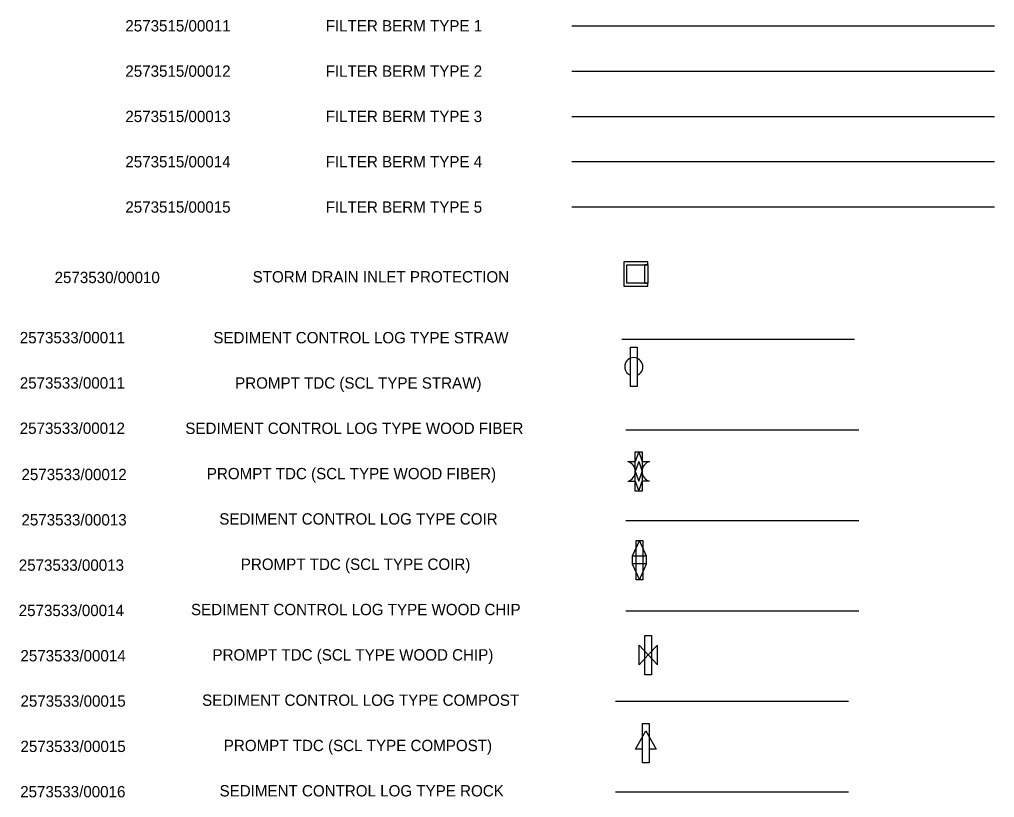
# Model space of a CAD drawing. Extents: x 2147712 to 2176316, y 2125036 to 2131746.
# Drawn here: x 2155076 to 2155722, y 2127332 to 2127847 of the extents above; entities that cross this region are included whole.
import ezdxf

# ---------------------------------------------------------------- set-up
doc = ezdxf.new("R2010")
doc.units = 0
doc.layers.add('DETAIL TXT', color=7, linetype='Continuous')
doc.layers.add('ERSN CTRL', color=7, linetype='Continuous')

msp = doc.modelspace()

# ---------------------------------------------------------------- linework, layer by layer
at = {"layer": 'ERSN CTRL'}
for p, q in [((2155442.09, 2127842.98), (2155722.13, 2127842.98)), ((2155442.09, 2127812.98), (2155722.13, 2127812.98)), ((2155442.09, 2127782.98), (2155722.13, 2127782.98)), ((2155442.09, 2127752.98), (2155722.13, 2127752.98)), ((2155442.09, 2127722.98), (2155722.13, 2127722.98)), ((2155484.13, 2127534.88), (2155484.13, 2127560.88)), ((2155484.13, 2127560.88), (2155488.58, 2127560.88)), ((2155486.36, 2127560.88), (2155484.13, 2127554.38)), ((2155486.36, 2127560.88), (2155488.58, 2127554.38)), ((2155488.58, 2127560.88), (2155488.58, 2127534.88)), ((2155479.13, 2127554.38), (2155484.13, 2127554.38)), ((2155486.36, 2127554.38), (2155484.13, 2127547.88)), ((2155486.36, 2127554.38), (2155488.58, 2127547.88)), ((2155488.58, 2127554.38), (2155493.58, 2127554.38)), ((2155484.13, 2127547.88), (2155486.36, 2127541.38)), ((2155486.36, 2127541.38), (2155488.58, 2127547.88)), ((2155479.13, 2127541.38), (2155484.13, 2127541.38)), ((2155484.13, 2127541.38), (2155486.36, 2127534.88)), ((2155486.36, 2127534.88), (2155488.58, 2127541.38)), ((2155493.58, 2127541.38), (2155488.58, 2127541.38)), ((2155488.58, 2127534.88), (2155484.13, 2127534.88)), ((2155484.59, 2127476.21), (2155484.59, 2127502.21)), ((2155484.59, 2127502.21), (2155489.04, 2127502.21)), ((2155489.04, 2127502.21), (2155489.04, 2127476.21)), ((2155491.54, 2127491.71), (2155482.09, 2127491.71)), ((2155491.54, 2127486.71), (2155482.09, 2127486.71)), ((2155489.04, 2127476.21), (2155484.59, 2127476.21))]:
    msp.add_line(p, q, dxfattribs=at)
for points in [[(2155492.53, 2127686.62), (2155476.53, 2127686.62), (2155476.53, 2127670.62), (2155492.53, 2127670.62), (2155492.53, 2127672.62), (2155478.53, 2127672.62), (2155478.53, 2127684.62), (2155492.53, 2127684.62)], [(2155490.53, 2127684.62), (2155492.53, 2127684.62), (2155492.53, 2127684.62), (2155490.53, 2127684.62)], [(2155490.53, 2127684.62), (2155492.53, 2127684.62), (2155492.53, 2127672.62), (2155490.53, 2127672.62)], [(2155492.53, 2127672.62), (2155490.53, 2127672.62), (2155490.53, 2127672.62), (2155492.53, 2127672.62)], [(2155486.82, 2127476.21), (2155491.54, 2127486.71), (2155491.54, 2127491.71), (2155486.82, 2127502.21), (2155482.09, 2127491.71), (2155482.09, 2127486.71)], [(2155486.7, 2127432.96), (2155492.74, 2127426.35), (2155486.7, 2127419.73)], [(2155498.78, 2127432.96), (2155492.74, 2127426.35), (2155498.78, 2127419.73)]]:
    msp.add_lwpolyline(points, close=True, dxfattribs=at)
for points in [[(2155475.14, 2127635.5), (2155629.47, 2127635.5)], [(2155480.87, 2127624.36), (2155480.87, 2127630.15), (2155485.31, 2127630.15), (2155485.31, 2127624.36)], [(2155485.31, 2127624.36), (2155485.31, 2127604.15), (2155480.87, 2127604.15), (2155480.87, 2127624.36)], [(2155477.85, 2127575.5), (2155632.18, 2127575.5)], [(2155477.85, 2127515.5), (2155632.18, 2127515.5)], [(2155477.85, 2127455.5), (2155632.18, 2127455.5)], [(2155490.52, 2127433.52), (2155490.52, 2127439.31), (2155494.96, 2127439.31), (2155494.96, 2127433.52)], [(2155494.96, 2127433.52), (2155494.96, 2127413.31), (2155490.52, 2127413.31), (2155490.52, 2127433.52)], [(2155471.11, 2127395.79), (2155625.44, 2127395.79)], [(2155488.88, 2127374.28), (2155488.88, 2127381.04), (2155493.33, 2127381.04), (2155493.33, 2127374.28)], [(2155488.88, 2127363.94), (2155484.19, 2127363.94), (2155491.02, 2127376.03), (2155497.94, 2127363.94), (2155493.33, 2127363.94)], [(2155493.33, 2127374.28), (2155493.33, 2127355.04), (2155488.88, 2127355.04), (2155488.88, 2127374.28)], [(2155471.11, 2127335.7), (2155625.44, 2127335.7)]]:
    msp.add_lwpolyline(points, dxfattribs=at)
for centre, radius, start, end in [((2155483.1, 2127617.19), 6.02, 291.55885, 248.44115), ((2155477.41, 2127547.88), 6.72, 284.86282, 75.13718), ((2155495.31, 2127547.88), 6.73, 104.86282, 255.13718)]:
    msp.add_arc(centre, radius, start, end, dxfattribs=at)

# ---------------------------------------------------------------- texts
at = {"layer": 'DETAIL TXT'}
for s, p in [('2573515/00011', (2155146.24, 2127839.18)), ('FILTER BERM TYPE 1', (2155278.98, 2127839.18)), ('2573515/00012', (2155146.24, 2127809.18)), ('FILTER BERM TYPE 2', (2155278.98, 2127809.18)), ('2573515/00013', (2155146.24, 2127779.18)), ('FILTER BERM TYPE 3', (2155278.98, 2127779.18)), ('2573515/00014', (2155146.24, 2127749.18)), ('FILTER BERM TYPE 4', (2155278.98, 2127749.18)), ('2573515/00015', (2155146.24, 2127719.18)), ('FILTER BERM TYPE 5', (2155278.98, 2127719.18)), ('2573530/00010', (2155099.35, 2127672.58)), ('STORM DRAIN INLET PROTECTION', (2155230.57, 2127672.98)), ('2573533/00011', (2155076.27, 2127632.72)), ('SEDIMENT CONTROL LOG TYPE STRAW', (2155204.53, 2127632.69)), ('2573533/00011', (2155076.27, 2127602.72)), ('PROMPT TDC (SCL TYPE STRAW)', (2155218.96, 2127602.69)), ('2573533/00012', (2155076.24, 2127572.72)), ('SEDIMENT CONTROL LOG TYPE WOOD FIBER', (2155185.97, 2127572.69)), ('2573533/00012', (2155077.39, 2127542.11)), ('PROMPT TDC (SCL TYPE WOOD FIBER)', (2155200.21, 2127542.69)), ('2573533/00013', (2155077.38, 2127512.11)), ('SEDIMENT CONTROL LOG TYPE COIR', (2155208.47, 2127512.69)), ('2573533/00013', (2155075.62, 2127482.11)), ('PROMPT TDC (SCL TYPE COIR)', (2155222.71, 2127482.69)), ('2573533/00014', (2155075.58, 2127452.11)), ('SEDIMENT CONTROL LOG TYPE WOOD CHIP', (2155189.72, 2127452.69)), ('2573533/00014', (2155076.72, 2127422.11)), ('PROMPT TDC (SCL TYPE WOOD CHIP)', (2155203.96, 2127422.69)), ('2573533/00015', (2155076.74, 2127392.11)), ('SEDIMENT CONTROL LOG TYPE COMPOST', (2155197.1, 2127392.69)), ('2573533/00015', (2155076.74, 2127362.11)), ('PROMPT TDC (SCL TYPE COMPOST)', (2155211.46, 2127362.69)), ('2573533/00016', (2155076.54, 2127332.11)), ('SEDIMENT CONTROL LOG TYPE ROCK', (2155208.65, 2127332.69))]:
    msp.add_text(s, height=7.5, dxfattribs=at).set_placement(p)

doc.saveas('drawing.dxf')
